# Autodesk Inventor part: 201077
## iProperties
Created: 2007-11
Part Number: 201077
Document SubType Name: Modeling
Designer: JJ
Density: 7.85 g/cm^3
Mass: 20.2939 g
Surface Area: 14.4088 cm^2
Volume: 2.58521 cm^3
Material: Steel
Description: MOTOR CONNECTING ROD
Component Category: Lower Component
Author: JJ
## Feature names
1. Extrusion1
2. Extrusion2
3. Fillet1
4. Revolution1
5. Mirror1
6. Chamfer2
7. Split1
8. Split2
